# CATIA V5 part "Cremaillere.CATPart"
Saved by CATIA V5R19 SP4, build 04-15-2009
Part number: Cremaillere
Bounding box of the stored display mesh (mm): x -48.852 to -15.102, y 2340 to 2385, z 1284.07 to 1784.07
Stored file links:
  G:\EU_thinkMotion\CFAO_2010\MMS_groupe1\MMS_groupe1\OK\rragonneau\rragonneau\Cremaillere.CATPart
  F:\Squelette\Deambulateur.CATProduct
  G:\EU_thinkMotion\CFAO_2010\MMS_groupe1\MMS_groupe1\OK\rragonneau\rragonneau\Montants.CATPart
  G:\EU_thinkMotion\CFAO_2010\MMS_groupe1\MMS_groupe1\OK\rragonneau\rragonneau\Siege.CATPart
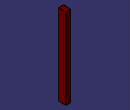
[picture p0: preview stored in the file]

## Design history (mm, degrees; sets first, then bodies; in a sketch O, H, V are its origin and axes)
External parameters (linked from other documents)
  `External.diam_moyeu_ext / epaisseur_bras&montant` = 60 mm
Set1
  Sketch1 on Plane1, origin (-584.0963, 2370, 0), H (1, 0, 0), V (0, 0, 1)
    line L1 (538.9942, 1784.0703) -> (568.9942, 1784.0703)
    line L2 (568.9942, 1784.0703) -> (568.9942, 1284.0703)
    line L3 (568.9942, 1284.0703) -> (539.0201, 1284.0703)
    line L4 (539.0201, 1284.0703) -> (538.9942, 1784.0703)
    length L1 = 30 {= `External.diam_moyeu_ext / epaisseur_bras&montant` /2}
    length L2 = 500
    horizontal: L1 H, L3 H
    vertical: L2 V
Set2
  Plane1: linked copy from another document
Body1 (main body)
  Pad1: profile Sketch1, direction (0, 1, 0), length 15 {= `External.diam_moyeu_ext / epaisseur_bras&montant` /4}, opposite side length 30 {= `External.diam_moyeu_ext / epaisseur_bras&montant` /2}
  Sketch2 on start face of Pad1, origin (0, 2340, 0), H (1, 0, 0), V (0, 0, 1)
    line L1 (-45.1021, 1784.0703) -> (-48.852, 1781.5703)
    point P1 (-45.1021, 1784.0703)
    point P2 (-48.852, 1781.5703)
    line L2 (-48.852, 1781.5703) -> (-45.1019, 1779.0703)
    point P3 (-45.1019, 1779.0703)
    reference projected point E1 (-45.1021, 1784.0703) from vertex [face of Pad1 from Sketch1.L1 | start face of Pad1 | face of Pad1 from Sketch1.L4]
    reference projected line E2 (-45.1021, 1784.0703) -> (-45.0762, 1284.0703) from edge [face of Pad1 from Sketch1.L4 | start face of Pad1]
    reference projected line E3 (-45.1021, 1784.0703) -> (-45.0762, 1284.0703) from edge [face of Pad1 from Sketch1.L4 | start face of Pad1]
    reference projected line E4 (-15.1021, 1784.0703) -> (-45.1021, 1784.0703) from edge [face of Pad1 from Sketch1.L1 | start face of Pad1]
    line L3 (-45.1021, 1784.0703) -> (-45.1019, 1779.0703)
    point P4 (-45.1021, 1784.0703)
    distance P2 E3 = 3.75 {= `External.diam_moyeu_ext / epaisseur_bras&montant` /16}
    distance P3 P1 = 5
    distance P2 E4 = 2.5
    coincidence: P1 E1, P3 E2, P4 L1, P1 P4
  Pad2: profile Sketch2, direction (0, 1, 0), length 10
  DatumCurve1
  RectPattern1: of Pad2, direction 1 instances 100, spacing 5, along edge [face of Pad1 from Sketch1.L4 | start face of Pad1]
Relations
  Pad1.FirstLimit.Length = `Paramètres externes\diam_moyeu_ext / epaisseur_bras&montant` /4+ (deactivated)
